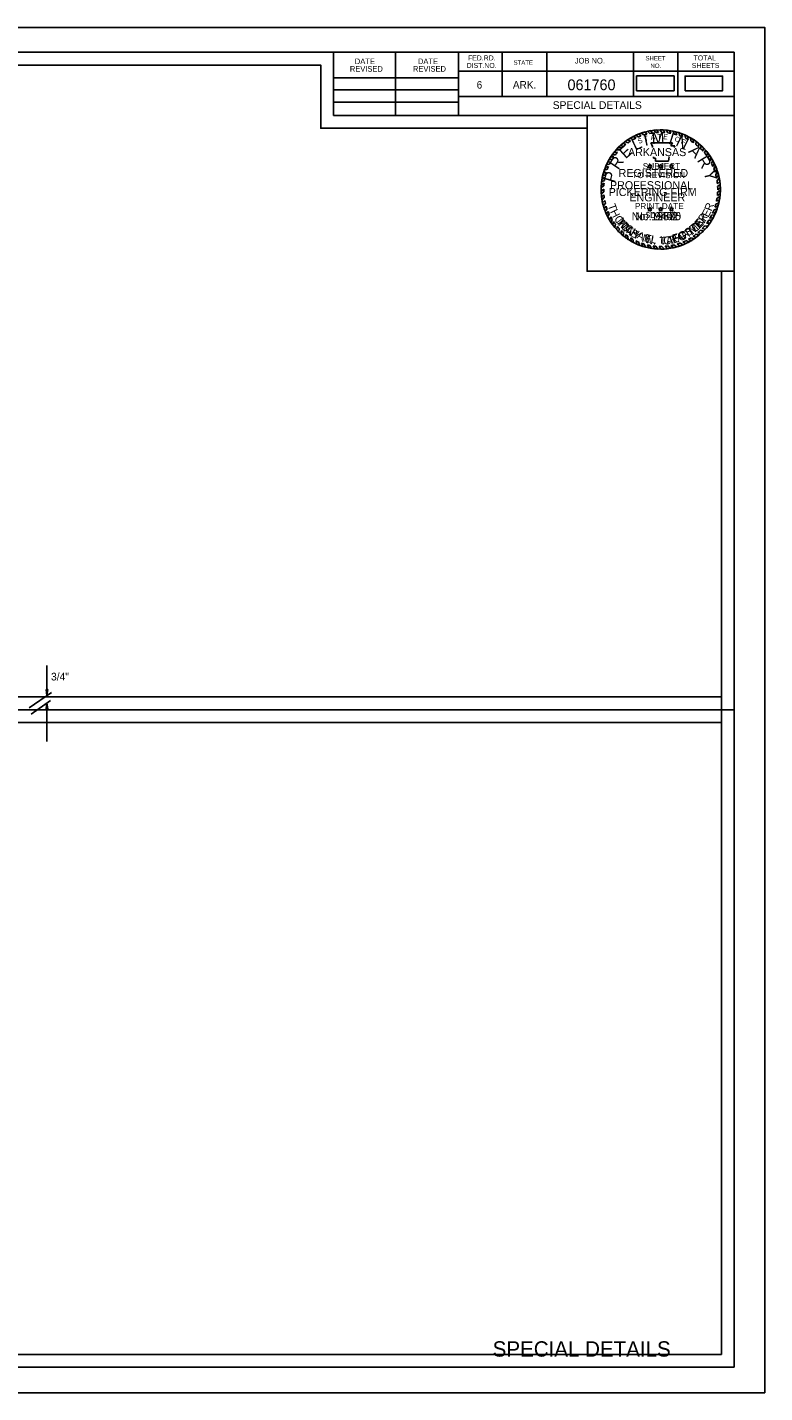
# Model space of a CAD drawing. Extents: x -12 to 321, y -4 to 209.
# Drawn here: x 205.7 to 320.9, y -4 to 209.4 of the extents above; entities that cross this region are included whole.
import ezdxf

# ---------------------------------------------------------------- set-up
doc = ezdxf.new("R2010")
doc.units = 0
for name, color, linetype in [('Default', 7, 'Continuous'), ('R_Border', 7, 'Continuous'), ('R_Border Notes', 7, 'Continuous'), ('R_Border Plan-Plan', 7, 'Continuous'), ('R_Border Title', 7, 'Continuous'), ('R_No Plot', 7, 'Continuous'), ('STAMP_PE_CRAFTON', 7, 'Continuous'), ('STAMP_PE_FOSTER', 7, 'Continuous'), ('STAMP_PE_SEAL-INFO', 7, 'Continuous'), ('STAMP_PE_TAEGTMEYER', 7, 'Continuous'), ('STAMP_PE_TXT', 7, 'Continuous'), ('STAMP_PRELIMINARY', 7, 'Continuous')]:
    doc.layers.add(name, color=color, linetype=linetype)

msp = doc.modelspace()

# ---------------------------------------------------------------- linework, layer by layer
at = {"layer": 'Default'}
for p, q in [((208.75, 104.94), (208.75, 109.65)), ((206, 103.03), (209.46, 105.43)), ((208.62, 105.87), (208.75, 104.94)), ((208.89, 105.87), (208.62, 105.87)), ((208.67, 105.87), (208.75, 105.25)), ((208.67, 105.87), (208.75, 105.12)), ((208.71, 105.87), (208.75, 105.56)), ((208.71, 105.87), (208.75, 105.43)), ((208.89, 105.87), (208.75, 104.94)), ((208.8, 105.87), (208.75, 105.56)), ((208.84, 105.87), (208.75, 105.25)), ((208.89, 105.87), (208.75, 105.12)), ((208.84, 105.87), (208.75, 105.43)), ((208.75, 105.87), (208.75, 105.74)), ((208.8, 105.87), (208.75, 105.74)), ((206.27, 102.05), (209.29, 104.18)), ((208.62, 102.85), (208.75, 103.78)), ((208.62, 102.85), (208.89, 102.85)), ((208.67, 102.85), (208.75, 103.65)), ((208.67, 102.85), (208.75, 103.47)), ((208.71, 102.85), (208.75, 103.34)), ((208.71, 102.85), (208.75, 103.16)), ((208.75, 97.74), (208.75, 103.78)), ((208.89, 102.85), (208.75, 103.78)), ((208.89, 102.85), (208.75, 103.65)), ((208.84, 102.85), (208.75, 103.47)), ((208.84, 102.85), (208.75, 103.34)), ((208.8, 102.85), (208.75, 103.16)), ((208.8, 102.85), (208.75, 103.03)), ((208.75, 102.85), (208.75, 103.03))]:
    msp.add_line(p, q, dxfattribs=at)
for points in [[(300.92, 199.44), (306.76, 199.44), (306.76, 201.75), (300.92, 201.75)], [(308.5, 199.43), (314.34, 199.43), (314.34, 201.74), (308.5, 201.74)]]:
    msp.add_lwpolyline(points, close=True, dxfattribs=at)
at = {"layer": 'R_Border'}
for p, q in [((0, 205.46), (316.18, 205.46)), ((253.54, 195.58), (253.54, 205.46)), ((263.22, 195.58), (263.22, 205.46)), ((273.08, 205.46), (273.08, 195.58)), ((279.92, 205.46), (279.92, 198.52)), ((286.86, 205.46), (286.86, 198.52)), ((300.44, 205.46), (300.44, 198.52)), ((307.38, 205.46), (307.38, 198.52)), ((316.18, 0), (316.18, 205.46)), ((253.54, 201.44), (273.08, 201.44)), ((316.18, 202.52), (273.08, 202.52)), ((316.18, 202.54), (316.18, 202.54)), ((253.54, 199.58), (273.08, 199.58)), ((316.18, 198.52), (273.08, 198.52)), ((276.04, 198.52), (316.18, 198.52)), ((253.54, 197.64), (273.08, 197.64)), ((316.18, 195.58), (253.54, 195.58)), ((316.18, 0), (0, 0))]:
    msp.add_line(p, q, dxfattribs=at)
at = {"layer": 'R_Border Plan-Plan'}
msp.add_line((0, 102.73), (316.18, 102.73), dxfattribs=at)
at = {"layer": 'R_No Plot'}
for points in [[(-12.41, 209.35), (320.93, 209.35), (320.93, -3.98), (-12.41, -3.98)], [(314.18, 104.73), (2, 104.73), (2, 203.46), (251.54, 203.46), (251.54, 193.58), (269.08, 193.58), (293.18, 193.58), (293.18, 171.25), (314.18, 171.25)], [(2, 203.46), (251.54, 203.46), (251.54, 193.58), (269.08, 193.58), (293.18, 193.58), (293.18, 171.25), (314.18, 171.25), (314.18, 2), (2, 2)], [(293.18, 195.58), (316.18, 195.58), (316.18, 171.25), (293.18, 171.25)], [(2, 100.73), (314.18, 100.73), (314.18, 2), (2, 2)]]:
    msp.add_lwpolyline(points, close=True, dxfattribs=at)
at = {"layer": 'STAMP_PE_SEAL-INFO'}
for p, q in [((299.9, 192.03), (300.34, 191.81)), ((300.35, 192.28), (300.82, 192.06)), ((300.78, 192.49), (301.17, 192.22)), ((301.29, 192.71), (301.59, 192.38)), ((301.64, 192.84), (302.02, 192.53)), ((302.23, 193.02), (302.52, 192.67)), ((302.62, 193.11), (302.97, 192.77)), ((303.1, 193.21), (303.4, 192.84)), ((303.62, 193.28), (303.9, 192.9)), ((304.35, 192.93), (304.04, 193.32)), ((304.85, 192.93), (304.57, 193.34)), ((305.31, 192.91), (305.05, 193.34)), ((305.81, 192.86), (305.52, 193.31)), ((306.24, 192.8), (305.98, 193.25)), ((306.8, 192.68), (306.63, 193.14)), ((307.2, 192.57), (307.04, 193.04)), ((307.65, 192.42), (307.51, 192.9)), ((308.07, 192.26), (307.93, 192.76)), ((308.53, 192.06), (308.43, 192.56)), ((308.98, 191.83), (308.89, 192.34)), ((309.37, 191.6), (309.33, 192.1)), ((297.72, 190.22), (298.24, 190.19)), ((298.04, 190.57), (298.59, 190.53)), ((298.38, 190.89), (298.84, 190.75)), ((298.72, 191.19), (299.25, 191.09)), ((299.1, 191.52), (299.55, 191.31)), ((299.52, 191.79), (299.96, 191.58)), ((303.15, 191.31), (306.5, 191.31)), ((303.27, 191.01), (303.15, 191.31)), ((303.38, 190.71), (303.27, 191.01)), ((303.39, 190.59), (303.38, 190.71)), ((306.5, 191.31), (306.27, 190.82)), ((306.27, 190.82), (306.9, 190.82)), ((306.9, 190.82), (306.76, 190.59)), ((309.8, 191.32), (309.77, 191.83)), ((310.16, 191.05), (310.2, 191.54)), ((310.61, 190.68), (310.63, 191.2)), ((310.92, 190.39), (310.99, 190.88)), ((311.28, 190.01), (311.35, 190.54)), ((311.55, 189.7), (311.69, 190.17)), ((296.2, 187.89), (296.7, 187.99)), ((296.38, 188.27), (296.88, 188.34)), ((296.61, 188.7), (297.1, 188.72)), ((296.86, 189.1), (297.38, 189.13)), ((297.1, 189.44), (297.6, 189.44)), ((297.37, 189.81), (297.92, 189.83)), ((303.58, 188.89), (303.55, 189.1)), ((303.89, 188.89), (303.58, 188.89)), ((303.89, 188.46), (303.89, 188.89)), ((305.92, 188.46), (303.89, 188.46)), ((305.94, 188.79), (305.92, 188.46)), ((306.01, 189.1), (305.94, 188.79)), ((311.88, 189.28), (312.01, 189.78)), ((312.1, 188.96), (312.28, 189.43)), ((312.41, 188.47), (312.59, 188.96)), ((312.61, 188.1), (312.83, 188.54)), ((312.84, 187.62), (313.06, 188.1)), ((295.96, 185.89), (295.5, 185.64)), ((295.6, 186.14), (296.07, 186.33)), ((295.7, 186.54), (296.18, 186.71)), ((295.86, 187.05), (296.35, 187.18)), ((296.01, 187.45), (296.52, 187.6)), ((312.98, 187.28), (313.24, 187.71)), ((313.17, 186.73), (313.44, 187.2)), ((313.28, 186.37), (313.57, 186.82)), ((313.41, 185.81), (313.73, 186.25)), ((313.48, 185.43), (313.84, 185.78)), ((295.78, 184.57), (295.36, 184.31)), ((295.77, 184.08), (295.36, 183.74)), ((295.82, 185), (295.38, 184.71)), ((295.77, 183.67), (295.38, 183.35)), ((295.88, 185.43), (295.43, 185.21)), ((313.55, 184.92), (313.92, 185.25)), ((313.58, 184.5), (313.97, 184.79)), ((313.58, 183.58), (314, 183.85)), ((313.59, 183.98), (314, 184.3)), ((295.81, 183.18), (295.44, 182.82)), ((295.86, 182.75), (295.5, 182.37)), ((295.94, 182.29), (295.6, 181.92)), ((296.03, 181.87), (295.72, 181.45)), ((296.15, 181.42), (295.86, 181)), ((313.15, 181.24), (313.64, 181.44)), ((313.29, 181.73), (313.77, 181.93)), ((313.4, 182.18), (313.86, 182.38)), ((313.49, 182.68), (313.93, 182.9)), ((313.54, 183.07), (313.98, 183.33)), ((296.3, 181), (296.01, 180.59)), ((296.46, 180.57), (296.2, 180.15)), ((296.63, 180.19), (296.41, 179.73)), ((296.87, 179.73), (296.68, 179.24)), ((297.1, 179.33), (296.92, 178.86)), ((312.19, 179.23), (312.67, 179.22)), ((312.36, 179.51), (312.87, 179.56)), ((312.64, 180), (313.12, 180.07)), ((312.8, 180.34), (313.29, 180.44)), ((313.01, 180.86), (313.49, 180.99)), ((297.31, 179.01), (297.2, 178.46)), ((297.59, 178.62), (297.49, 178.09)), ((297.89, 178.25), (297.8, 177.73)), ((298.19, 177.91), (298.13, 177.39)), ((298.52, 177.58), (298.49, 177.05)), ((298.86, 177.27), (298.86, 176.74)), ((310.5, 177.27), (310.97, 177.14)), ((310.91, 177.64), (311.35, 177.51)), ((311.16, 177.9), (311.64, 177.82)), ((311.55, 178.34), (312.01, 178.26)), ((311.85, 178.73), (312.36, 178.73)), ((299.22, 176.98), (299.24, 176.45)), ((299.56, 176.73), (299.6, 176.21)), ((299.99, 176.45), (300.05, 175.93)), ((300.34, 176.24), (300.43, 175.73)), ((300.82, 175.99), (300.97, 175.47)), ((301.19, 175.82), (301.36, 175.31)), ((301.68, 175.63), (301.89, 175.13)), ((302.09, 175.49), (302.32, 175)), ((302.6, 175.36), (302.81, 174.89)), ((303, 175.27), (303.24, 174.81)), ((303.5, 175.19), (303.74, 174.75)), ((303.93, 175.14), (304.21, 174.71)), ((304.42, 175.11), (304.72, 174.7)), ((304.88, 175.11), (305.22, 174.72)), ((305.4, 175.14), (305.72, 174.76)), ((305.84, 175.18), (306.21, 174.83)), ((306.28, 175.25), (306.67, 174.91)), ((306.77, 175.36), (307.15, 175.03)), ((307.23, 175.48), (307.65, 175.19)), ((307.73, 175.65), (308.17, 175.38)), ((308.14, 175.81), (308.57, 175.55)), ((308.6, 176.02), (309.09, 175.81)), ((309.01, 176.23), (309.43, 176)), ((309.43, 176.48), (309.88, 176.28)), ((309.77, 176.71), (310.21, 176.52)), ((310.23, 177.05), (310.7, 176.9))]:
    msp.add_line(p, q, dxfattribs=at)
for radius, start, end in [(9.32, 117.6544, 120.8099), (8.91, 115.6869, 119.1583), (9.32, 111.3124, 114.7026), (8.91, 110.3086, 113.1659), (9.32, 105.2339, 109.0352), (8.91, 104.0352, 107.3615), (9.32, 99.7525, 102.7765), (8.91, 98.258, 101.0329), (9.32, 93.9381, 96.5517), (8.91, 92.1102, 95.0367), (9.32, 87.7298, 90.6707), (8.91, 85.9628, 88.9097), (9.32, 81.9732, 84.8236), (8.91, 79.9264, 82.696), (9.32, 75.3125, 77.9426), (8.91, 73.5575, 76.2314), (9.32, 69.6061, 72.3058), (8.91, 67.6248, 70.504), (9.32, 63.1329, 66.2704), (8.91, 61.1558, 64.3784), (9.32, 56.9003, 60.0942), (9.32, 135.4021, 138.3031), (8.91, 133.1331, 136.2562), (9.32, 129.7326, 132.5376), (8.91, 127.5297, 130.9683), (9.32, 123.6199, 126.5906), (8.91, 121.9746, 125.11), (8.91, 54.9238, 58.2702), (8.91, 48.3016, 52.0395), (9.32, 50.3492, 53.7159), (8.91, 42.2212, 45.5512), (9.32, 44.3405, 47.3929), (9.32, 38.1247, 41.2316), (9.32, 152.864, 155.5189), (9.32, 147.0072, 149.899), (8.91, 151.0315, 153.573), (9.32, 141.6056, 144.4486), (8.91, 145.0197, 148.2104), (8.91, 139.301, 142.5873), (8.91, 36.135, 39.5311), (8.91, 29.9032, 33.6645), (9.32, 31.9614, 35.4294), (8.91, 23.7732, 27.2211), (9.32, 25.9391, 29.0125), (9.32, 170.0003, 172.6878), (9.32, 164.3068, 166.894), (9.32, 158.4077, 161.0701), (8.91, 167.9048, 170.9039), (8.91, 162.4331, 165.0013), (8.91, 156.3402, 159.2319), (8.91, 17.6802, 21.4251), (9.32, 19.9538, 23.3141), (8.91, 11.5444, 15.2364), (9.32, 13.8421, 17.4447), (9.32, 7.5852, 10.8621), (9.32, 175.7409, 178.2066), (9.32, 181.7251, 184.1626), (8.91, 179.6454, 182.2633), (8.91, 173.73, 176.4734), (8.91, 5.7599, 9.0606), (8.91, 353.8632, 357.1274), (8.91, 359.7329, 3.0639), (9.32, 1.7215, 4.7268), (9.32, 355.7156, 358.9569), (9.32, 187.4204, 190.1927), (9.32, 193.0369, 195.9973), (8.91, 185.4539, 188.234), (8.91, 191.2274, 193.9858), (8.91, 196.9675, 199.8353), (8.91, 341.777, 345.0925), (8.91, 348.0778, 351.3435), (9.32, 343.8925, 347.035), (9.32, 349.8305, 353.0885), (9.32, 198.8967, 201.6281), (9.32, 204.5479, 207.4328), (8.91, 202.7761, 205.4791), (9.32, 210.8636, 213.6571), (8.91, 208.7883, 211.7934), (8.91, 323.5851, 327.4407), (8.91, 329.5549, 333.2076), (9.32, 325.4405, 328.9872), (8.91, 335.6038, 339.1858), (9.32, 331.4037, 334.9332), (9.32, 337.3837, 340.9933), (9.32, 216.6115, 219.491), (8.91, 214.1838, 217.2747), (9.32, 222.48, 225.3801), (8.91, 220.3909, 223.3056), (8.91, 226.2494, 229.2407), (8.91, 310.7744, 314.3161), (9.32, 312.4518, 315.6633), (8.91, 316.6531, 320.3711), (9.32, 318.2846, 321.8043), (9.32, 228.3665, 231.348), (8.91, 232.229, 234.9336), (9.32, 234.295, 236.9452), (8.91, 238.2223, 240.8353), (9.32, 240.1977, 242.8613), (8.91, 244.3204, 246.9486), (9.32, 246.576, 249.1558), (8.91, 250.3491, 253.1216), (9.32, 252.5967, 255.3252), (8.91, 256.505, 259.1192), (8.91, 262.3783, 265.2012), (8.91, 268.3215, 271.277), (8.91, 274.6157, 277.4486), (8.91, 280.3459, 283.5814), (9.32, 282.3199, 285.3702), (8.91, 286.6423, 289.9783), (9.32, 288.5709, 291.9733), (8.91, 292.8745, 296.1185), (9.32, 294.6481, 298.2166), (8.91, 299.0768, 302.1724), (9.32, 300.621, 303.8703), (8.91, 304.823, 308.5143), (9.32, 306.3721, 310.208), (9.32, 258.4433, 261.1398), (9.32, 264.1978, 267.1009), (9.32, 270.2548, 273.3361), (9.32, 276.4239, 279.4357)]:
    msp.add_arc((304.68, 184.02), radius, start, end, dxfattribs=at)
at = {"layer": 'STAMP_PE_TXT'}
for p, q in [((302.86, 187.59), (302.66, 187.74)), ((302.66, 187.74), (302.91, 187.74)), ((302.91, 187.74), (302.98, 187.97)), ((302.98, 187.97), (303.06, 187.74)), ((303.06, 187.74), (303.3, 187.74)), ((303.3, 187.74), (303.1, 187.59)), ((304.56, 187.59), (304.36, 187.74)), ((304.36, 187.74), (304.6, 187.74)), ((304.6, 187.74), (304.68, 187.97)), ((304.68, 187.97), (304.76, 187.74)), ((304.76, 187.74), (305, 187.74)), ((305, 187.74), (304.8, 187.59)), ((306.26, 187.59), (306.06, 187.74)), ((306.06, 187.74), (306.3, 187.74)), ((306.3, 187.74), (306.38, 187.97)), ((306.38, 187.97), (306.45, 187.74)), ((306.45, 187.74), (306.7, 187.74)), ((306.7, 187.74), (306.5, 187.59)), ((302.78, 187.36), (302.86, 187.59)), ((302.98, 187.5), (302.78, 187.36)), ((303.18, 187.36), (302.98, 187.5)), ((303.1, 187.59), (303.18, 187.36)), ((304.48, 187.36), (304.56, 187.59)), ((304.68, 187.5), (304.48, 187.36)), ((304.88, 187.36), (304.68, 187.5)), ((304.8, 187.59), (304.88, 187.36)), ((306.18, 187.36), (306.26, 187.59)), ((306.38, 187.5), (306.18, 187.36)), ((306.58, 187.36), (306.38, 187.5)), ((306.5, 187.59), (306.58, 187.36)), ((302.86, 180.89), (302.66, 181.03)), ((302.66, 181.03), (302.91, 181.03)), ((302.78, 180.65), (302.86, 180.89)), ((302.98, 180.8), (302.78, 180.65)), ((302.91, 181.03), (302.98, 181.26)), ((302.98, 181.26), (303.06, 181.03)), ((303.18, 180.65), (302.98, 180.8)), ((303.06, 181.03), (303.3, 181.03)), ((303.3, 181.03), (303.1, 180.89)), ((303.1, 180.89), (303.18, 180.65)), ((304.56, 180.89), (304.36, 181.03)), ((304.36, 181.03), (304.6, 181.03)), ((304.48, 180.65), (304.56, 180.89)), ((304.68, 180.8), (304.48, 180.65)), ((304.6, 181.03), (304.68, 181.26)), ((304.68, 181.26), (304.76, 181.03)), ((304.88, 180.65), (304.68, 180.8)), ((304.76, 181.03), (305, 181.03)), ((305, 181.03), (304.8, 180.89)), ((304.8, 180.89), (304.88, 180.65)), ((306.26, 180.89), (306.06, 181.03)), ((306.06, 181.03), (306.3, 181.03)), ((306.18, 180.65), (306.26, 180.89)), ((306.38, 180.8), (306.18, 180.65)), ((306.3, 181.03), (306.38, 181.26)), ((306.38, 181.26), (306.45, 181.03)), ((306.58, 180.65), (306.38, 180.8)), ((306.45, 181.03), (306.7, 181.03)), ((306.7, 181.03), (306.5, 180.89)), ((306.5, 180.89), (306.58, 180.65))]:
    msp.add_line(p, q, dxfattribs=at)
at = {"layer": 'STAMP_PRELIMINARY'}
msp.add_circle((304.68, 184.02), 9.32, dxfattribs=at)

# ---------------------------------------------------------------- texts
at = {"layer": 'Default'}
msp.add_text('3/4"', height=1.2, dxfattribs=at).set_placement((209.4, 107.3))
at = {"layer": 'R_Border'}
for s, height, p in [('FED.RD.', 0.782, (274.56, 204.18)), ('SHEET', 0.684, (302.3, 204.18)), ('TOTAL', 0.782, (309.82, 204.18)), ('REVISED', 0.879, (256.1, 202.42)), ('DATE', 0.879, (256.88, 203.6)), ('REVISED', 0.879, (265.96, 202.42)), ('DATE', 0.879, (266.74, 203.6)), ('DIST.NO.', 0.782, (274.36, 203)), ('STATE', 0.684, (281.68, 203.5)), ('JOB NO.', 0.879, (291.26, 203.7)), ('NO.', 0.684, (303.08, 203)), ('SHEETS', 0.782, (309.54, 203)), ('6', 1.17, (275.92, 199.78)), ('ARK.', 1.172, (281.58, 199.78))]:
    msp.add_text(s, height=height, dxfattribs=at).set_placement(p)
at = {"layer": 'R_Border Notes'}
for s, height, p in [('061760', 1.68, (290.12, 199.53)), ('SPECIAL DETAILS', 1.2, (287.81, 196.6))]:
    msp.add_text(s, height=height, dxfattribs=at).set_placement(p)
at = {"layer": 'R_Border Title'}
msp.add_text('SPECIAL DETAILS', height=2.4, dxfattribs=at).set_placement((278.42, 1.65))
at = {"layer": 'STAMP_PE_CRAFTON'}
for s, rotation, p in [('T', 310.7442, (297.65, 178.92)), ('N', 49.2411, (310.96, 178.04)), ('O', 317.6422, (298.31, 178.11)), ('N', 324.4537, (299.16, 177.32)), ('Y', 331.1686, (300.19, 176.61)), ('A', 20.5125, (307.36, 175.78)), ('F', 28.7821, (308.34, 176.15)), ('T', 34.1136, (309.26, 176.66)), ('O', 41.8391, (310.12, 177.26)), ('N', 347.4752, (302.25, 175.69)), ('.', 356.8926, (303.48, 175.41)), ('C', 6.0117, (305.15, 175.36)), ('R', 14.8189, (306.25, 175.48))]:
    msp.add_text(s, height=1.25, rotation=rotation, dxfattribs=at).set_placement(p)
msp.add_text('No. 12370', height=1.25, dxfattribs=at).set_placement((300.14, 179.22))
at = {"layer": 'STAMP_PE_FOSTER'}
for s, rotation, p in [('M', 308.339, (297.8, 179.04)), ('E', 46.9613, (310.68, 178.01)), ('R', 54.5031, (311.4, 178.83)), ('I', 314.1842, (298.59, 178.11)), ('C', 319.8733, (298.95, 177.75)), ('H', 327.7235, (299.88, 177.02)), ('A', 335.7276, (300.86, 176.44)), ('E', 343.5779, (302, 175.97)), ('F', 15.8691, (306.71, 175.78)), ('O', 23.719, (307.76, 176.1)), ('S', 31.7234, (308.87, 176.63)), ('T', 39.4194, (309.82, 177.26)), ('L', 350.8115, (303.05, 175.69)), ('L', 1.2666, (304.59, 175.53)), ('.', 6.8035, (305.64, 175.59))]:
    msp.add_text(s, height=1.2, rotation=rotation, dxfattribs=at).set_placement(p)
msp.add_text('No. 9402', height=1.25, dxfattribs=at).set_placement((300.67, 179.22))
at = {"layer": 'STAMP_PE_TAEGTMEYER'}
for s, rotation, p in [('T', 289.646, (296.37, 181.53)), ('R', 69.57, (312.63, 180.54)), ('H', 296.7339, (296.73, 180.55)), ('O', 303.7708, (297.33, 179.44)), ('M', 314.2033, (297.98, 178.49)), ('E', 46.8094, (310.72, 177.8)), ('Y', 53.9986, (311.46, 178.61)), ('E', 63.0984, (312.13, 179.56)), ('A', 321.0594, (298.94, 177.52)), ('S', 327.8239, (299.77, 176.88)), ('G', 23.3052, (307.68, 175.88)), ('T', 31.466, (308.78, 176.38)), ('M', 39.3, (309.68, 176.92)), ('N', 344.2727, (301.67, 175.87)), ('.', 350.6464, (302.88, 175.54)), ('T', 3.0061, (304.54, 175.34)), ('A', 8.9826, (305.59, 175.4)), ('E', 17.6836, (306.63, 175.55))]:
    msp.add_text(s, height=1.25, rotation=rotation, dxfattribs=at).set_placement(p)
msp.add_text('No. 19605', height=1.25, dxfattribs=at).set_placement((300.14, 179.22))
at = {"layer": 'STAMP_PE_TXT'}
for s, rotation, p in [('S', 23.5541, (301.28, 191.13)), ('T', 16.311, (302.2, 191.5)), ('A', 9.0679, (303.16, 191.75)), ('T', 1.8248, (304.15, 191.88)), ('E', 355.2002, (305.06, 191.89)), ('O', 342.2506, (306.79, 191.61)), ('F', 335.0075, (307.75, 191.27))]:
    msp.add_text(s, height=0.781, rotation=rotation, dxfattribs=at).set_placement(p)
for s, p in [('ARKANSAS', (299.57, 189.23)), ('REGISTERED', (298.1, 185.96)), ('PROFESSIONAL', (296.75, 184.06)), ('ENGINEER', (299.79, 182.16))]:
    msp.add_text(s, height=1.25, dxfattribs=at).set_placement(p)
at = {"layer": 'STAMP_PRELIMINARY'}
for s, rotation, p in [('I', 12.5248, (302.22, 190.81)), ('M', 3.1074, (303.32, 191.12)), ('I', 342.3164, (305.78, 191.19)), ('N', 333.9382, (306.89, 190.91)), ('E', 42.3578, (299.21, 188.72)), ('L', 25.513, (300.69, 190.05)), ('A', 315.6579, (308.92, 189.89)), ('R', 56.2292, (298.05, 186.99)), ('R', 301.3831, (310.29, 188.57)), ('P', 73.913, (297.5, 184.96)), ('Y', 283.2593, (311.38, 186.79))]:
    msp.add_text(s, height=1.8, rotation=rotation, dxfattribs=at).set_placement(p)
for s, height, p in [('SUBJECT', 0.96, (301.88, 187.17)), ('TO REVISION', 0.96, (300.22, 185.79)), ('PICKERING FIRM', 1.25, (296.55, 182.99)), ('PRINT DATE', 0.96, (300.64, 180.94)), ('$DATE$', 0.96, (302.31, 179.55))]:
    msp.add_text(s, height=height, dxfattribs=at).set_placement(p)

doc.saveas('drawing.dxf')
